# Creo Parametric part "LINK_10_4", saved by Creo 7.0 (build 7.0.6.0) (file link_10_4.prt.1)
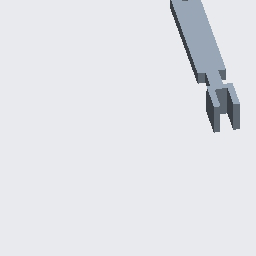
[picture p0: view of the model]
Units: millimeter Newton Second (mmNs); MM, TONNE, SECS

Created from: XX_MMNS_PART_SOLID_ABS.PRT

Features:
  1. datum plane "RIGHT"
  2. datum plane "TOP"
  3. datum plane "FRONT"
  4. coordinate system
  5. extrusion "Extrude 1"
  6. extruded cut "Extrude 2"
  7. extrusion "Extrude 3"
  8. extrusion "Extrude 4"
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
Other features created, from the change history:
  extruded cut "Extrude 5"

Surfaces: 16 plane, 2 cylinder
